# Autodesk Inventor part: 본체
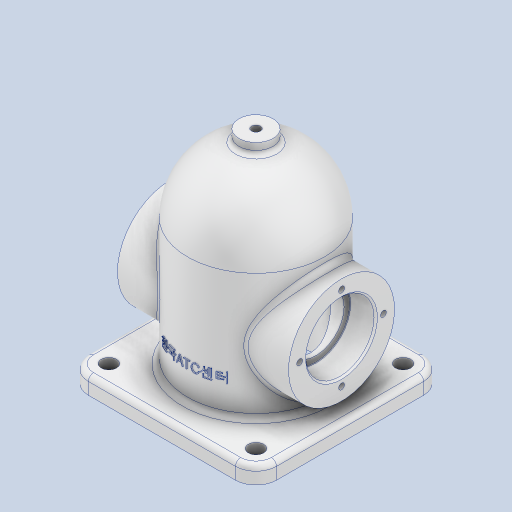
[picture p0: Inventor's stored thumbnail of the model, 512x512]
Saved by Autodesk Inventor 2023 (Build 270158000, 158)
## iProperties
Created: 2025-04
Part Number: 본체
Material: 알루미늄 6061
Document SubType Name: Modeling
Designer: Admin
Density: 2.7 g/cm^3
Appearance: 알루미늄 - 평지
Mass: 866.007 g
Surface Area: 800.421 cm^2
Volume: 320.743 cm^3
Author: Admin
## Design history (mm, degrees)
sketch "스케치1"
  geometry: L1 (-56, 0)-(56, 0) reference; L2 (0, -59.8)-(0, 99.8) reference; L3 (-40, -37)-(40, -37); L4 (40, -37)-(40, 37); L5 (40, 37)-(-40, 37); L6 (-40, 37)-(-40, -37); L7 (-40, -37)-(40, 37); L8 (40, -37)-(-40, 37); A1 r 40 centre (0, 37) between (40, 37) and (-40, 37); 3 further points
  constraints: 12 end point, 3 midpoint, 2 parallel, 2 point on circle, 1 centre point, 1 horizontal, 1 perpendicular
  dimensions: "d4" = 74 distance between parallel lines of L3 L5; "d27" = 40 radius of A1
revolve "회전1" sketch "스케치1" stored, may be unused: angle "d6" = 90 deg
sketch "스케치2"
  geometry: L1 (-55, 55)-(55, 55); L2 (55, 55)-(55, -55); L3 (55, -55)-(-55, -55); L4 (-55, -55)-(-55, 55); L5 (-55, 55)-(55, -55); L6 (55, 55)-(-55, -55); 1 further point
  constraints: 12 end point, 2 midpoint, 2 parallel, 1 horizontal, 1 perpendicular
  dimensions: "d7" = 110 distance of L1.end L2.end; "d8" = 110 distance of L2.end L3.end
extrude "돌출1" join sketch "스케치2" distance "d9" = 10; taper "d10" = 0 deg
sketch "스케치3"
  geometry: L1 (-62.6, 0)-(46.6, 0) reference; L2 (0, -77)-(0, 77) reference; L3 (1, 53.337)-(1, -53.714); L4 (-47, -55)-(-47, 55) reference; C1 r 31 at (0, 0); 1 further point
  constraints: 2 end point, 1 centre point, 1 coincident, 1 vertical
  dimensions: "d11" = 48 distance between parallel lines of L3 L4; "d12" = 62 diameter of C1
extrude "돌출2" join sketch "스케치3" stored distance "d13" = 100; taper "d14" = 0 deg
sketch "스케치4"
  geometry: C1 r 10 at (0, 0); 1 further point
  constraints: 1 centre point, 1 coincident
  dimensions: "d15" = 20 diameter of C1
extrude "돌출3" join sketch "스케치4" distance "d16" = 82; taper "d17" = 0 deg
sketch "스케치5"
  geometry: L1 (30.551, 1)-(-29.029, 1); L2 (55, -47)-(-55, -47) reference; L3 (0, -71.8)-(0, 101.8) reference; C1 r 16.5 at (0, 1); C2 r 20 at (0, 1); 1 further point
  constraints: 2 centre point, 2 end point, 2 point on line, 1 coincident, 1 horizontal
  dimensions: "d66" = 48 distance between parallel lines of L1 L2; "d67" = 33 diameter of C1; "d68" = 40 diameter of C2
sketch "스케치6"
  geometry: L1 (0, -72.8)-(0, 107.8) reference; L2 (-51.735, 1)-(51.369, 1); L3 (55, -47)-(-55, -47) reference; C1 r 20 at (0, 1); C2 r 16.5 at (0, 1); 1 further point
  constraints: 2 centre point, 2 end point, 2 point on line, 1 coincident, 1 horizontal
  dimensions: "d69" = 48 distance between parallel lines of L2 L3; "d70" = 40 diameter of C1; "d71" = 33 diameter of C2
extrude "돌출6" cut sketch "스케치6" stored distance "d25" = 15; taper "d26" = 0 deg
sketch "스케치7" dims "d28" = 32
  geometry: L1 (40, -37)-(-40, -37) reference; L2 (-32, 37)-(32, 37); L3 (32, 37)-(32, -37); L4 (32, -37)-(-32, -37); L5 (-32, -37)-(-32, 37); L6 (-32, 37)-(32, -37); L7 (32, 37)-(-32, -37); L8 (-77, 0)-(77, 0) reference; L9 (0, -72.8)-(0, 107.8) reference; 4 further points
  constraints: 12 end point, 3 midpoint, 2 parallel, 1 horizontal, 1 perpendicular, 1 point on line, 3 other
revolve "회전2" sketch "스케치7" stored, may be unused: angle "d29" = 90 deg
sketch "스케치8"
  geometry: C1 r 32 at (0, 0); 1 further point
  constraints: 1 centre point, 1 coincident
  dimensions: "d30" = 32 radius of C1
extrude "돌출7" cut sketch "스케치8" distance "d31" = 15; taper "d32" = 0 deg
sketch "스케치9"
  geometry: L1 (0, -71.8)-(0, 101.8) reference; L2 (-77, 0)-(77, 0) reference; 2 further points
  constraints: 1 point on line
  dimensions: "d33" = 51 diameter of point (0, 25.5) L2
hole "구멍1" sketch "스케치9" at (0, 25.5) diameter "d34" = 3.45873; stored, may be unused: countersink angle "d38" = 90 deg, drill point angle "d40" = 118 deg; dims "d35" = 8, "d36" = 8, "d37" = 10, "d39" = 10.8
sketch "스케치10"
  geometry: 2 further points
  constraints: 1 coincident
hole "구멍2" sketch "스케치10" at (0, 0) diameter "d44" = 5.1881; stored, may be unused: countersink angle "d48" = 90 deg, drill point angle "d50" = 118 deg; dims "d45" = 20, "d46" = 4, "d47" = 2, "d49" = 16
fillet "모깎기1" dims "d51" = 12
sketch "스케치11"
  geometry: L1 (-77, 0)-(77, 0) reference; L2 (0, 77)-(0, -77) reference; C1 r 4.5 at (-43, 43); C2 r 4.5 at (43, 43); C3 r 4.5 at (-43, -43); C4 r 4.5 at (43, -43); A1 r 12 centre (-43, 43) between (-43, 55) and (-55, 43) reference; 1 further point
  constraints: 4 centre point, 3 symmetric about line, 1 concentric, 3 other
  dimensions: "d52" = 9 diameter of C1
extrude "돌출8" cut sketch "스케치11" stored distance "d53" = 15; taper "d54" = 0 deg
fillet "모깎기2" dims "d55" = 3
node "작업 평면1"
sketch "스케치13"
  geometry: L1 (-77, 0)-(77, 0) reference; L2 (0, -72.8)-(0, 107.8) reference; L3 (43, -47)-(-43, -47) reference; 2 further points
  constraints: 1 point on line, 1 other
  dimensions: "d63" = 30 distance from line of L3 point (0, -17)
feature "엠보싱2" sketch "스케치13" dims "d64" = 0.5, "d65" = 0
extrude "돌출9" cut sketch "스케치6" distance "d72" = 15; taper "d73" = 0 deg
extrude "돌출10" cut sketch "스케치5" distance "d74" = 15; taper "d75" = 0 deg
chamfer "모따기2" distance "d79" = 1; stored, may be unused: second distance "d80" = 2, angle "d81" = 45 deg
fillet "모깎기4" dims "d82" = 0.3
feature "ɷ耀ɹ耀ɻ耀ɽ耀ɿ耀ʁ耀ʃ耀ʅ耀" dims "d4" = 74, "d6" = 90 deg, "d7" = 110, "d8" = 110, "d9" = 10, "d10" = 0, "d11" = 48, "d12" = 62, "d13" = 100, "d14" = 0, "d15" = 20, "d16" = 82, "d17" = 0, "d25" = 15, "d26" = 0, "d27" = 40, "d28" = 32, "d29" = 90 deg, "d30" = 32, "d31" = 15, "d32" = 0, "d33" = 51, "d34" = 3.45873, "d35" = 8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
node "솔리드1"
mirror "미러1"
pattern_circular "원형 패턴2" dims angle "d77" = 360 deg
mirror "미러2"
feature "A9D066F2-1C7D-4E18-AEED-F7BC21143FA4" dims "d34" = 3.45873, "d35" = 8, "d36" = 8, "d37" = 10, "d38" = 90 deg, "d39" = 10.8, "d40" = 118 deg
